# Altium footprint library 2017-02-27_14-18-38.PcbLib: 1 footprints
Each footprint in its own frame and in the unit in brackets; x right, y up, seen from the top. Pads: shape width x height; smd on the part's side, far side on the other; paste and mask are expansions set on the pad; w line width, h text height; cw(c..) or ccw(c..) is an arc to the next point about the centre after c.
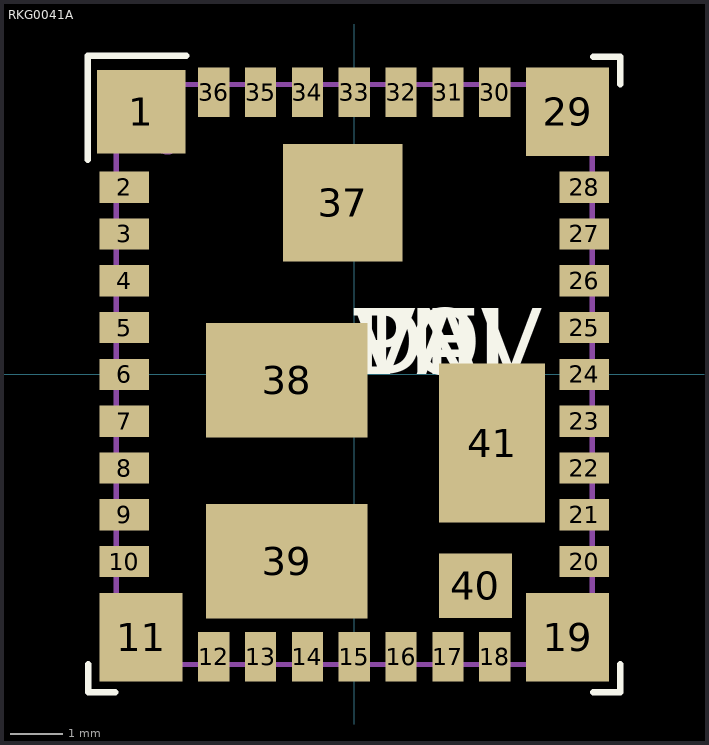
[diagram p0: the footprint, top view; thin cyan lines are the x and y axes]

## RKG0041A [mm]
pads (41):
  rect 1.702x1.6 smd paste-0.102 mask+0.051: 1(-4.1,5.05)
  rect 0.95x0.6 smd paste-0.475 mask+0.051: 2(-4.42,3.6) 3(-4.42,2.7) 4(-4.42,1.8) 5(-4.42,0.9) 6(-4.42,0) 7(-4.42,-0.9) 8(-4.42,-1.8) 9(-4.42,-2.7) 10(-4.42,-3.6) 20(4.42,-3.6) 21(4.42,-2.7) 22(4.42,-1.8) 23(4.42,-0.9) 24(4.42,0) 25(4.42,0.9) 26(4.42,1.8) 27(4.42,2.7) 28(4.42,3.6)
  rect 1.6x1.7 smd paste-0.8 mask+0.051: 11(-4.1,-5.05) 19(4.1,-5.05) 29(4.1,5.05)
  rect 0.6x0.95 smd paste-0.475 mask+0.051: 12(-2.7,-5.425) 13(-1.8,-5.425) 14(-0.9,-5.425) 15(0,-5.425) 16(0.9,-5.425) 17(1.8,-5.425) 18(2.7,-5.425) 30(2.7,5.425) 31(1.8,5.425) 32(0.9,5.425) 33(0,5.425) 34(-0.9,5.425) 35(-1.8,5.425) 36(-2.7,5.425)
  rect 2.3x2.25 smd paste-1.15 mask+0.051: 37(-0.22,3.3)
  rect 3.1x2.2 smd paste-1.1 mask+0.051: 38(-1.3,-0.11) 39(-1.3,-3.59)
  rect 1.4x1.24 smd paste-0.7 mask+0.051: 40(2.33,-4.06)
  rect 2.04x3.05 smd paste-1.02 mask+0.051: 41(2.65,-1.32)
Top Overlay:
  lines w0.127: -5.125,4.13 -5.125,6.125 -3.23,6.125 ; -5.115,-5.575 -5.115,-6.11 -4.6,-6.11 ; 4.6,-6.11 5.115,-6.11 5.115,-5.575 ; 4.6,6.11 5.115,6.11 5.115,5.575
  text "TOL" at 0,0 h1.27
  text "VAL" at 0,0 h1.27
  text "PN" at 0,0 h1.27
  text "DEV" at 0,0 h1.27
Top Paste:
  drawing of 52 lines, arcs and shapes, not listed
Top Solder:
  region: -1.37,4.425 -1.37,2.175 -0.77,2.175 -0.77,4.425
  region: 0.33,4.425 0.33,2.175 0.93,2.175 0.93,4.425
Mechanical 13:
  circle w0.1: c-3.6,4.475 r0.2
  lines w0.1: -4.575,-5.575 4.575,-5.575 4.575,5.575 -4.575,5.575 -4.575,-5.575
  text ".Designator" at -2.15,-0.275 h1.27
3D body: height 0.25, standoff 0, extent 0,0 0.254,0.254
